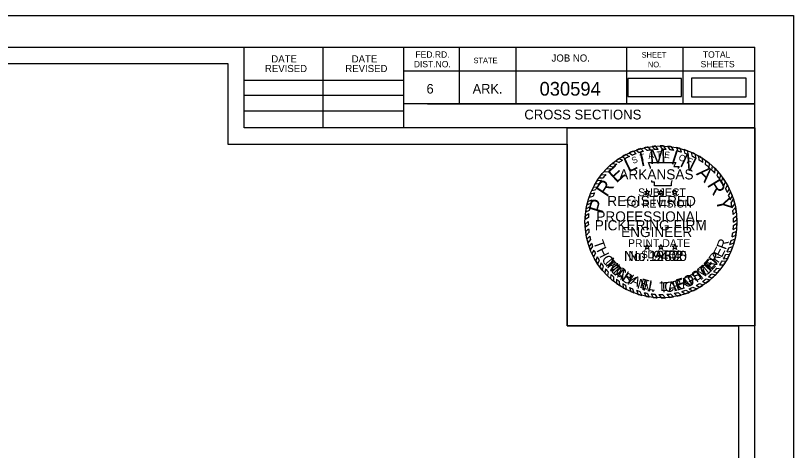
# Model space of a CAD drawing. Extents: x 1368713 to 1370673, y 380279 to 380950.
# Drawn here: x 1370577.1 to 1370672.6, y 380897.1 to 380950.4 of the extents above; entities that cross this region are included whole.
import ezdxf

# ---------------------------------------------------------------- set-up
doc = ezdxf.new("R2010")
doc.units = 0
for name, color, linetype in [('R_Border', 7, 'Continuous'), ('R_Border Notes', 7, 'Continuous'), ('R_No Plot', 7, 'Continuous'), ('R_Water', 7, 'Continuous'), ('STAMP_PE_CRAFTON', 7, 'Continuous'), ('STAMP_PE_FOSTER', 7, 'Continuous'), ('STAMP_PE_SEAL-INFO', 7, 'Continuous'), ('STAMP_PE_TAEGTMEYER', 7, 'Continuous'), ('STAMP_PE_TXT', 7, 'Continuous'), ('STAMP_PRELIMINARY', 7, 'Continuous')]:
    doc.layers.add(name, color=color, linetype=linetype)

msp = doc.modelspace()

# ---------------------------------------------------------------- linework, layer by layer
at = {"layer": 'R_Border'}
for p, q in [((1370351.629, 380946.552), (1370667.809, 380946.552)), ((1370605.169, 380936.672), (1370605.169, 380946.552)), ((1370614.849, 380936.672), (1370614.849, 380946.552)), ((1370624.709, 380946.552), (1370624.709, 380936.672)), ((1370631.549, 380946.552), (1370631.549, 380939.612)), ((1370638.489, 380946.552), (1370638.489, 380939.612)), ((1370652.069, 380946.552), (1370652.069, 380939.612)), ((1370659.009, 380946.552), (1370659.009, 380939.612)), ((1370667.809, 380741.092), (1370667.809, 380946.552)), ((1370667.809, 380943.612), (1370624.709, 380943.612)), ((1370667.809, 380943.632), (1370667.809, 380943.632)), ((1370605.169, 380942.532), (1370624.709, 380942.532)), ((1370605.169, 380940.672), (1370624.709, 380940.672)), ((1370667.809, 380939.612), (1370624.709, 380939.612)), ((1370627.669, 380939.612), (1370667.809, 380939.612)), ((1370605.169, 380938.732), (1370624.709, 380938.732)), ((1370667.809, 380936.672), (1370605.169, 380936.672))]:
    msp.add_line(p, q, dxfattribs=at)
at = {"layer": 'R_No Plot'}
for points in [[(1370339.221, 380950.446), (1370672.561, 380950.446), (1370672.561, 380737.109), (1370339.221, 380737.109)], [(1370665.809, 380845.822), (1370353.629, 380845.822), (1370353.629, 380944.552), (1370603.169, 380944.552), (1370603.169, 380934.672), (1370620.709, 380934.672), (1370644.809, 380934.672), (1370644.809, 380912.339), (1370665.809, 380912.339)], [(1370353.629, 380944.552), (1370603.169, 380944.552), (1370603.169, 380934.672), (1370620.709, 380934.672), (1370644.809, 380934.672), (1370644.809, 380912.339), (1370665.809, 380912.339), (1370665.809, 380743.092), (1370353.629, 380743.092)], [(1370644.809, 380936.672), (1370667.809, 380936.672), (1370667.809, 380912.339), (1370644.809, 380912.339)]]:
    msp.add_lwpolyline(points, close=True, dxfattribs=at)
at = {"layer": 'R_Water'}
for points in [[(1370660.067, 380940.456), (1370666.751, 380940.456), (1370666.751, 380942.767), (1370660.067, 380942.767)], [(1370652.257, 380940.519), (1370658.821, 380940.519), (1370658.821, 380942.705), (1370652.257, 380942.705)]]:
    msp.add_lwpolyline(points, close=True, dxfattribs=at)
at = {"layer": 'STAMP_PE_SEAL-INFO'}
for p, q in [((1370654.247, 380934.206), (1370654.603, 380933.863)), ((1370654.73, 380934.302), (1370655.029, 380933.935)), ((1370655.245, 380934.376), (1370655.526, 380933.993)), ((1370655.981, 380934.022), (1370655.669, 380934.415)), ((1370656.479, 380934.026), (1370656.2, 380934.436)), ((1370656.937, 380934.006), (1370656.678, 380934.43)), ((1370657.442, 380933.955), (1370657.15, 380934.399)), ((1370657.868, 380933.89), (1370657.611, 380934.346)), ((1370658.43, 380933.772), (1370658.256, 380934.231)), ((1370651.982, 380933.372), (1370652.445, 380933.147)), ((1370652.413, 380933.584), (1370652.802, 380933.309)), ((1370652.921, 380933.799), (1370653.215, 380933.474)), ((1370653.268, 380933.927), (1370653.649, 380933.622)), ((1370653.859, 380934.109), (1370654.147, 380933.762)), ((1370658.832, 380933.663), (1370658.673, 380934.132)), ((1370659.284, 380933.517), (1370659.142, 380933.996)), ((1370659.702, 380933.357), (1370659.558, 380933.853)), ((1370660.163, 380933.151), (1370660.061, 380933.649)), ((1370660.609, 380932.922), (1370660.522, 380933.431)), ((1370660.997, 380932.695), (1370660.957, 380933.196)), ((1370650.35, 380932.284), (1370650.879, 380932.183)), ((1370650.727, 380932.611), (1370651.182, 380932.406)), ((1370651.147, 380932.877), (1370651.589, 380932.675)), ((1370651.534, 380933.121), (1370651.966, 380932.898)), ((1370654.782, 380932.406), (1370658.126, 380932.406)), ((1370654.903, 380932.098), (1370654.782, 380932.406)), ((1370658.126, 380932.406), (1370657.901, 380931.914)), ((1370661.431, 380932.409), (1370661.4, 380932.924)), ((1370661.792, 380932.142), (1370661.826, 380932.629)), ((1370662.238, 380931.77), (1370662.258, 380932.292)), ((1370649.348, 380931.316), (1370649.87, 380931.277)), ((1370649.671, 380931.66), (1370650.215, 380931.619)), ((1370650.006, 380931.983), (1370650.465, 380931.845)), ((1370655.007, 380931.8), (1370654.903, 380932.098)), ((1370655.014, 380931.686), (1370655.007, 380931.8)), ((1370657.901, 380931.914), (1370658.534, 380931.914)), ((1370658.534, 380931.914), (1370658.389, 380931.686)), ((1370662.551, 380931.477), (1370662.62, 380931.976)), ((1370662.91, 380931.104), (1370662.977, 380931.63)), ((1370648.724, 380930.535), (1370649.229, 380930.53)), ((1370649.002, 380930.904), (1370649.551, 380930.927)), ((1370663.184, 380930.788), (1370663.32, 380931.259)), ((1370663.508, 380930.37), (1370663.643, 380930.87)), ((1370663.728, 380930.055), (1370663.905, 380930.519)), ((1370648.012, 380929.366), (1370648.511, 380929.431)), ((1370648.244, 380929.79), (1370648.733, 380929.81)), ((1370648.49, 380930.191), (1370649.006, 380930.224)), ((1370655.206, 380929.977), (1370655.179, 380930.195)), ((1370655.52, 380929.977), (1370655.206, 380929.977)), ((1370655.52, 380929.547), (1370655.52, 380929.977)), ((1370657.55, 380929.547), (1370655.52, 380929.547)), ((1370657.565, 380929.885), (1370657.55, 380929.547)), ((1370657.643, 380930.195), (1370657.565, 380929.885)), ((1370664.036, 380929.558), (1370664.218, 380930.049)), ((1370664.235, 380929.191), (1370664.462, 380929.636)), ((1370647.641, 380928.545), (1370648.145, 380928.691)), ((1370647.824, 380928.977), (1370648.327, 380929.081)), ((1370664.466, 380928.707), (1370664.693, 380929.192)), ((1370664.607, 380928.37), (1370664.87, 380928.804)), ((1370647.334, 380927.636), (1370647.811, 380927.804)), ((1370647.49, 380928.139), (1370647.975, 380928.275)), ((1370664.801, 380927.821), (1370665.072, 380928.296)), ((1370664.909, 380927.457), (1370665.203, 380927.909)), ((1370647.508, 380926.523), (1370647.062, 380926.301)), ((1370647.593, 380926.982), (1370647.128, 380926.733)), ((1370647.229, 380927.228), (1370647.699, 380927.421)), ((1370665.042, 380926.898), (1370665.361, 380927.345)), ((1370665.111, 380926.518), (1370665.465, 380926.871)), ((1370647.412, 380925.662), (1370646.991, 380925.406)), ((1370647.449, 380926.088), (1370647.012, 380925.807)), ((1370665.177, 380926.009), (1370665.55, 380926.345)), ((1370665.21, 380925.591), (1370665.6, 380925.882)), ((1370647.396, 380925.169), (1370646.991, 380924.834)), ((1370647.402, 380924.762), (1370647.011, 380924.437)), ((1370665.211, 380924.667), (1370665.63, 380924.944)), ((1370665.222, 380925.073), (1370665.627, 380925.394)), ((1370647.436, 380924.267), (1370647.064, 380923.91)), ((1370647.487, 380923.838), (1370647.133, 380923.464)), ((1370665.121, 380923.773), (1370665.564, 380923.992)), ((1370665.171, 380924.161), (1370665.606, 380924.418)), ((1370647.566, 380923.379), (1370647.227, 380923.011)), ((1370647.66, 380922.96), (1370647.347, 380922.545)), ((1370664.922, 380922.821), (1370665.394, 380923.023)), ((1370665.03, 380923.273), (1370665.485, 380923.468)), ((1370647.783, 380922.513), (1370647.489, 380922.095)), ((1370647.924, 380922.09), (1370647.643, 380921.678)), ((1370664.641, 380921.947), (1370665.123, 380922.078)), ((1370664.775, 380922.327), (1370665.266, 380922.528)), ((1370648.091, 380921.663), (1370647.829, 380921.241)), ((1370648.262, 380921.28), (1370648.035, 380920.819)), ((1370648.497, 380920.822), (1370648.306, 380920.332)), ((1370664.266, 380921.096), (1370664.754, 380921.164)), ((1370664.427, 380921.433), (1370664.915, 380921.529)), ((1370648.733, 380920.418), (1370648.549, 380919.947)), ((1370648.935, 380920.106), (1370648.826, 380919.554)), ((1370663.822, 380920.317), (1370664.299, 380920.311)), ((1370663.993, 380920.598), (1370664.494, 380920.652)), ((1370649.216, 380919.716), (1370649.114, 380919.185)), ((1370649.52, 380919.338), (1370649.433, 380918.818)), ((1370649.823, 380919.001), (1370649.761, 380918.478)), ((1370662.791, 380918.996), (1370663.268, 380918.911)), ((1370663.174, 380919.429), (1370663.636, 380919.35)), ((1370663.482, 380919.823), (1370663.987, 380919.826)), ((1370650.145, 380918.675), (1370650.115, 380918.146)), ((1370650.49, 380918.363), (1370650.486, 380917.834)), ((1370650.849, 380918.068), (1370650.868, 380917.544)), ((1370661.86, 380918.14), (1370662.327, 380917.994)), ((1370662.13, 380918.364), (1370662.602, 380918.235)), ((1370662.536, 380918.737), (1370662.977, 380918.599)), ((1370651.188, 380917.819), (1370651.224, 380917.3)), ((1370651.615, 380917.537), (1370651.676, 380917.024)), ((1370651.965, 380917.331), (1370652.056, 380916.818)), ((1370652.446, 380917.081), (1370652.603, 380916.56)), ((1370660.233, 380917.111), (1370660.717, 380916.899)), ((1370660.641, 380917.324), (1370661.058, 380917.092)), ((1370661.055, 380917.569), (1370661.505, 380917.374)), ((1370661.399, 380917.797), (1370661.838, 380917.608)), ((1370652.819, 380916.912), (1370652.992, 380916.402)), ((1370653.311, 380916.72), (1370653.521, 380916.218)), ((1370653.721, 380916.585), (1370653.947, 380916.096)), ((1370654.229, 380916.447), (1370654.441, 380915.981)), ((1370654.626, 380916.361), (1370654.873, 380915.903)), ((1370655.127, 380916.279), (1370655.367, 380915.839)), ((1370655.563, 380916.232), (1370655.837, 380915.803)), ((1370656.048, 380916.205), (1370656.35, 380915.792)), ((1370656.508, 380916.203), (1370656.851, 380915.807)), ((1370657.026, 380916.23), (1370657.352, 380915.85)), ((1370657.465, 380916.276), (1370657.837, 380915.918)), ((1370657.91, 380916.346), (1370658.298, 380916.006)), ((1370658.402, 380916.45), (1370658.78, 380916.125)), ((1370658.862, 380916.574), (1370659.278, 380916.277)), ((1370659.354, 380916.737), (1370659.797, 380916.469)), ((1370659.774, 380916.902), (1370660.197, 380916.641))]:
    msp.add_line(p, q, dxfattribs=at)
for radius, start, end in [(9.323, 99.75254, 102.77648), (9.323, 93.93815, 96.55172), (9.323, 87.72979, 90.67067), (9.323, 81.97315, 84.82355), (9.323, 75.31251, 77.94263), (9.323, 117.65441, 120.80988), (9.323, 111.31242, 114.70259), (8.914, 110.30864, 113.16588), (9.323, 105.23389, 109.03519), (8.914, 104.03521, 107.36155), (8.914, 98.25799, 101.03289), (8.914, 92.11016, 95.03666), (8.914, 85.96279, 88.9097), (8.914, 79.92642, 82.69597), (8.914, 73.55748, 76.23144), (9.323, 69.60611, 72.30577), (8.914, 67.62483, 70.50398), (9.323, 63.13288, 66.2704), (9.323, 56.90029, 60.09423), (9.323, 129.73259, 132.53764), (9.323, 123.61993, 126.59063), (8.914, 121.97456, 125.11001), (8.914, 115.68692, 119.15827), (8.914, 61.15575, 64.37837), (8.914, 54.92383, 58.27016), (9.323, 50.3492, 53.71593), (9.323, 135.40208, 138.30314), (8.914, 133.13306, 136.25623), (8.914, 127.52969, 130.96829), (8.914, 48.30163, 52.03953), (8.914, 42.22116, 45.55119), (9.323, 44.3405, 47.39292), (9.323, 141.60556, 144.44865), (8.914, 139.30101, 142.58729), (8.914, 36.13503, 39.53106), (9.323, 38.12472, 41.23157), (9.323, 31.96138, 35.42937), (9.323, 147.00719, 149.89904), (8.914, 151.03153, 153.57304), (8.914, 145.01972, 148.21036), (8.914, 29.90321, 33.66454), (9.323, 25.93909, 29.01247), (9.323, 158.40766, 161.07015), (9.323, 152.86398, 155.51889), (8.914, 156.34018, 159.23194), (8.914, 23.77322, 27.22114), (9.323, 19.95381, 23.31409), (9.323, 164.3068, 166.89395), (8.914, 162.43309, 165.00133), (8.914, 17.68022, 21.42509), (9.323, 13.84205, 17.44468), (9.323, 170.0003, 172.68778), (8.914, 167.90481, 170.90393), (8.914, 11.54445, 15.23639), (8.914, 5.7599, 9.06056), (9.323, 7.58519, 10.86211), (9.323, 175.74093, 178.2066), (8.914, 173.73, 176.47337), (8.914, 359.73289, 3.06392), (9.323, 1.72155, 4.72681), (9.323, 181.72508, 184.16255), (8.914, 179.64537, 182.26333), (8.914, 353.86319, 357.12742), (9.323, 355.71562, 358.95694), (9.323, 187.42037, 190.19271), (8.914, 185.45389, 188.23401), (8.914, 348.07782, 351.34355), (9.323, 349.83047, 353.08845), (9.323, 193.03695, 195.99732), (8.914, 191.22736, 193.98583), (8.914, 341.77699, 345.09248), (9.323, 343.89247, 347.03502), (9.323, 198.89671, 201.62812), (8.914, 196.96751, 199.83526), (8.914, 335.6038, 339.18578), (9.323, 337.38367, 340.99332), (9.323, 204.54793, 207.43282), (8.914, 202.77613, 205.47915), (8.914, 208.78826, 211.79343), (8.914, 329.55488, 333.20757), (9.323, 331.40371, 334.93315), (9.323, 210.86355, 213.65709), (8.914, 214.18375, 217.27474), (8.914, 323.58513, 327.44069), (9.323, 325.44052, 328.98725), (9.323, 216.61154, 219.49098), (8.914, 220.39088, 223.30564), (8.914, 316.65308, 320.37109), (9.323, 318.28455, 321.80429), (9.323, 222.47995, 225.38008), (9.323, 228.36648, 231.34802), (8.914, 226.24938, 229.24068), (8.914, 232.22904, 234.93361), (8.914, 304.82299, 308.51428), (9.323, 306.37206, 310.20799), (8.914, 310.77436, 314.31605), (9.323, 312.45177, 315.66328), (9.323, 234.29502, 236.94517), (8.914, 238.22227, 240.83529), (9.323, 240.1977, 242.86128), (8.914, 244.32043, 246.94859), (8.914, 292.87452, 296.11851), (8.914, 299.07679, 302.17235), (9.323, 300.62101, 303.87026), (9.323, 246.57598, 249.15579), (8.914, 250.34912, 253.12157), (9.323, 252.59667, 255.32518), (8.914, 256.50505, 259.11916), (8.914, 262.37828, 265.20115), (8.914, 268.3215, 271.27698), (8.914, 274.61565, 277.44863), (8.914, 280.34588, 283.58137), (9.323, 282.31994, 285.37019), (8.914, 286.64233, 289.97826), (9.323, 288.57086, 291.97334), (9.323, 294.64808, 298.21662), (9.323, 258.44328, 261.13983), (9.323, 264.19784, 267.10092), (9.323, 270.25484, 273.33609), (9.323, 276.42389, 279.43574)]:
    msp.add_arc((1370656.309, 380925.114), radius, start, end, dxfattribs=at)
at = {"layer": 'STAMP_PE_TXT'}
for p, q in [((1370654.488, 380928.686), (1370654.29, 380928.83)), ((1370654.29, 380928.83), (1370654.535, 380928.83)), ((1370654.413, 380928.452), (1370654.488, 380928.686)), ((1370654.611, 380928.597), (1370654.413, 380928.452)), ((1370654.535, 380928.83), (1370654.611, 380929.063)), ((1370654.611, 380929.063), (1370654.687, 380928.83)), ((1370654.809, 380928.452), (1370654.611, 380928.597)), ((1370654.687, 380928.83), (1370654.932, 380928.83)), ((1370654.932, 380928.83), (1370654.734, 380928.686)), ((1370654.734, 380928.686), (1370654.809, 380928.452)), ((1370656.186, 380928.686), (1370655.988, 380928.83)), ((1370655.988, 380928.83), (1370656.233, 380928.83)), ((1370656.111, 380928.452), (1370656.186, 380928.686)), ((1370656.309, 380928.597), (1370656.111, 380928.452)), ((1370656.233, 380928.83), (1370656.309, 380929.063)), ((1370656.309, 380929.063), (1370656.385, 380928.83)), ((1370656.507, 380928.452), (1370656.309, 380928.597)), ((1370656.385, 380928.83), (1370656.63, 380928.83)), ((1370656.63, 380928.83), (1370656.432, 380928.686)), ((1370656.432, 380928.686), (1370656.507, 380928.452)), ((1370657.884, 380928.686), (1370657.686, 380928.83)), ((1370657.686, 380928.83), (1370657.931, 380928.83)), ((1370657.809, 380928.452), (1370657.884, 380928.686)), ((1370658.007, 380928.597), (1370657.809, 380928.452)), ((1370657.931, 380928.83), (1370658.007, 380929.063)), ((1370658.007, 380929.063), (1370658.083, 380928.83)), ((1370658.205, 380928.452), (1370658.007, 380928.597)), ((1370658.083, 380928.83), (1370658.328, 380928.83)), ((1370658.328, 380928.83), (1370658.13, 380928.686)), ((1370658.13, 380928.686), (1370658.205, 380928.452)), ((1370654.488, 380921.979), (1370654.29, 380922.123)), ((1370654.29, 380922.123), (1370654.535, 380922.123)), ((1370654.413, 380921.745), (1370654.488, 380921.979)), ((1370654.611, 380921.89), (1370654.413, 380921.745)), ((1370654.535, 380922.123), (1370654.611, 380922.356)), ((1370654.611, 380922.356), (1370654.687, 380922.123)), ((1370654.809, 380921.745), (1370654.611, 380921.89)), ((1370654.687, 380922.123), (1370654.932, 380922.123)), ((1370654.932, 380922.123), (1370654.734, 380921.979)), ((1370654.734, 380921.979), (1370654.809, 380921.745)), ((1370656.186, 380921.979), (1370655.988, 380922.123)), ((1370655.988, 380922.123), (1370656.233, 380922.123)), ((1370656.111, 380921.745), (1370656.186, 380921.979)), ((1370656.309, 380921.89), (1370656.111, 380921.745)), ((1370656.233, 380922.123), (1370656.309, 380922.356)), ((1370656.309, 380922.356), (1370656.385, 380922.123)), ((1370656.507, 380921.745), (1370656.309, 380921.89)), ((1370656.385, 380922.123), (1370656.63, 380922.123)), ((1370656.63, 380922.123), (1370656.432, 380921.979)), ((1370656.432, 380921.979), (1370656.507, 380921.745)), ((1370657.884, 380921.979), (1370657.686, 380922.123)), ((1370657.686, 380922.123), (1370657.931, 380922.123)), ((1370657.809, 380921.745), (1370657.884, 380921.979)), ((1370658.007, 380921.89), (1370657.809, 380921.745)), ((1370657.931, 380922.123), (1370658.007, 380922.356)), ((1370658.007, 380922.356), (1370658.083, 380922.123)), ((1370658.205, 380921.745), (1370658.007, 380921.89)), ((1370658.083, 380922.123), (1370658.328, 380922.123)), ((1370658.328, 380922.123), (1370658.13, 380921.979)), ((1370658.13, 380921.979), (1370658.205, 380921.745))]:
    msp.add_line(p, q, dxfattribs=at)
at = {"layer": 'STAMP_PRELIMINARY'}
msp.add_circle((1370656.309, 380925.114), 9.323, dxfattribs=at)

# ---------------------------------------------------------------- texts
at = {"layer": 'R_Border'}
for s, height, p in [('FED.RD.', 0.7819, (1370626.189, 380945.272)), ('JOB NO.', 0.8792, (1370642.889, 380944.792)), ('SHEET', 0.684, (1370653.929, 380945.272)), ('TOTAL', 0.7819, (1370661.449, 380945.272)), ('DATE', 0.8792, (1370608.507, 380944.688)), ('DATE', 0.8792, (1370618.367, 380944.688)), ('DIST.NO.', 0.7819, (1370625.989, 380944.092)), ('STATE', 0.684, (1370633.309, 380944.592)), ('NO.', 0.684, (1370654.709, 380944.092)), ('SHEETS', 0.7819, (1370661.169, 380944.092)), ('REVISED', 0.8792, (1370607.727, 380943.508)), ('REVISED', 0.8792, (1370617.587, 380943.508)), ('6', 1.172, (1370627.549, 380940.872)), ('ARK.', 1.1723, (1370633.209, 380940.872))]:
    msp.add_text(s, height=height, rotation=360, dxfattribs=at).set_placement(p)
at = {"layer": 'R_Border Notes'}
for s, height, p in [('030594', 1.68, (1370641.42, 380940.617)), ('CROSS SECTIONS', 1.2, (1370639.548, 380937.69))]:
    msp.add_text(s, height=height, rotation=360, dxfattribs=at).set_placement(p)
at = {"layer": 'STAMP_PE_CRAFTON'}
for s, rotation, p in [('T', 310.74416, (1370649.275, 380920.012)), ('No. 12370', 360, (1370651.771, 380920.311)), ('O', 317.64216, (1370649.942, 380919.201)), ('O', 41.83906, (1370661.744, 380918.355)), ('N', 49.24107, (1370662.591, 380919.136)), ('N', 324.45371, (1370650.788, 380918.416)), ('T', 34.11362, (1370660.886, 380917.753)), ('Y', 331.16864, (1370651.821, 380917.7)), ('N', 347.47515, (1370653.876, 380916.784)), ('R', 14.81888, (1370657.877, 380916.57)), ('A', 20.51248, (1370658.99, 380916.87)), ('F', 28.78207, (1370659.97, 380917.244)), ('C', 6.01169, (1370656.78, 380916.455)), ('.', 356.89262, (1370655.105, 380916.507))]:
    msp.add_text(s, height=1.25, rotation=rotation, dxfattribs=at).set_placement(p)
at = {"layer": 'STAMP_PE_FOSTER'}
for s, height, rotation, p in [('No. 9402', 1.25, 360, (1370652.295, 380920.311)), ('R', 1.2, 54.5031, (1370663.033, 380919.925)), ('M', 1.2, 308.33902, (1370649.425, 380920.136)), ('I', 1.2, 314.18423, (1370650.223, 380919.199)), ('T', 1.2, 39.41938, (1370661.451, 380918.354)), ('E', 1.2, 46.96131, (1370662.31, 380919.104)), ('C', 1.2, 319.87327, (1370650.577, 380918.845)), ('H', 1.2, 327.72349, (1370651.506, 380918.109)), ('S', 1.2, 31.72336, (1370660.5, 380917.727)), ('A', 1.2, 335.72761, (1370652.487, 380917.527)), ('E', 1.2, 343.5779, (1370653.624, 380917.057)), ('L', 1.2, 350.81148, (1370654.683, 380916.779)), ('F', 1.2, 15.86908, (1370658.344, 380916.869)), ('O', 1.2, 23.71897, (1370659.388, 380917.197)), ('L', 1.2, 1.26658, (1370656.222, 380916.623)), ('.', 1.2, 6.80354, (1370657.269, 380916.681))]:
    msp.add_text(s, height=height, rotation=rotation, dxfattribs=at).set_placement(p)
at = {"layer": 'STAMP_PE_TAEGTMEYER'}
for s, rotation, p in [('T', 289.64597, (1370648.003, 380922.624)), ('R', 69.57001, (1370664.254, 380921.629)), ('H', 296.73386, (1370648.363, 380921.64)), ('E', 63.0984, (1370663.755, 380920.647)), ('O', 303.77078, (1370648.956, 380920.532)), ('No. 19605', 360, (1370651.771, 380920.311)), ('Y', 53.99864, (1370663.086, 380919.707)), ('M', 314.20329, (1370649.611, 380919.581)), ('E', 46.80938, (1370662.347, 380918.892)), ('A', 321.0594, (1370650.573, 380918.616)), ('T', 31.46601, (1370660.409, 380917.469)), ('M', 39.30005, (1370661.307, 380918.012)), ('S', 327.82385, (1370651.399, 380917.972)), ('N', 344.27273, (1370653.296, 380916.966)), ('E', 17.68363, (1370658.259, 380916.646)), ('G', 23.30524, (1370659.309, 380916.976)), ('T', 3.00609, (1370656.173, 380916.435)), ('A', 8.98261, (1370657.22, 380916.49)), ('.', 350.64643, (1370654.508, 380916.634))]:
    msp.add_text(s, height=1.25, rotation=rotation, dxfattribs=at).set_placement(p)
at = {"layer": 'STAMP_PE_TXT'}
for s, height, rotation, p in [('T', 0.781, 16.311, (1370653.831, 380932.59)), ('A', 0.781, 9.0679, (1370654.793, 380932.843)), ('T', 0.781, 1.82479, (1370655.779, 380932.972)), ('E', 0.781, 355.20019, (1370656.69, 380932.981)), ('O', 0.781, 342.25065, (1370658.416, 380932.704)), ('S', 0.781, 23.5541, (1370652.908, 380932.218)), ('F', 0.781, 335.00755, (1370659.382, 380932.366)), ('ARKANSAS', 1.25, 360, (1370651.201, 380930.325)), ('REGISTERED', 1.25, 360, (1370649.726, 380927.055)), ('PROFESSIONAL', 1.25, 360, (1370648.377, 380925.154)), ('ENGINEER', 1.25, 360, (1370651.418, 380923.252))]:
    msp.add_text(s, height=height, rotation=rotation, dxfattribs=at).set_placement(p)
at = {"layer": 'STAMP_PRELIMINARY'}
for s, height, rotation, p in [('I', 1.8, 12.52485, (1370653.847, 380931.901)), ('M', 1.8, 3.10738, (1370654.945, 380932.21)), ('I', 1.8, 342.31637, (1370657.412, 380932.277)), ('N', 1.8, 333.9382, (1370658.52, 380932.003)), ('L', 1.8, 25.51305, (1370652.318, 380931.142)), ('E', 1.8, 42.35784, (1370650.835, 380929.811)), ('A', 1.8, 315.65789, (1370660.554, 380930.978)), ('R', 1.8, 301.38306, (1370661.922, 380929.664)), ('R', 1.8, 56.22922, (1370649.68, 380928.078)), ('SUBJECT', 0.96, 360, (1370653.509, 380928.264)), ('P', 1.8, 73.91301, (1370649.13, 380926.055)), ('TO REVISION', 0.96, 360, (1370651.844, 380926.879)), ('Y', 1.8, 283.25926, (1370663.011, 380927.877)), ('PICKERING FIRM', 1.25, 360, (1370648.182, 380924.077)), ('PRINT DATE', 0.96, 360, (1370652.266, 380922.03)), ('$DATE$', 0.96, 360, (1370653.943, 380920.645))]:
    msp.add_text(s, height=height, rotation=rotation, dxfattribs=at).set_placement(p)

doc.saveas('drawing.dxf')
